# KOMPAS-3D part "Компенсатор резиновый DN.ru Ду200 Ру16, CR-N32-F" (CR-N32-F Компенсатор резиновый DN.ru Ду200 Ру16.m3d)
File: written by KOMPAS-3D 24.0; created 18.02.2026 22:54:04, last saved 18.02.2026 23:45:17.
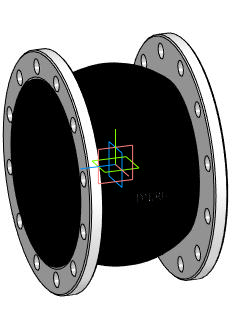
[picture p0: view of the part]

Document properties: Автор: DN.RU; Полное имя файла: D:\PROJECT CAD\DN.RU\...178(2)(ACTUALE). CR-N32-F Компенсатор резиновый DN.ru Ру10-16\CR-N32-F Компенсатор резиновый DN.ru Ру10-16\DN200_PN16\CR-N32-F Компенсатор резиновый DN.ru Ду200 Ру16.m3d

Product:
- Body: Твердое тело2  | qty 1
    Масса: 46.886983
- Part/product: Компенсатор резиновый DN.ru Ду200 Ру16  | designation CR-N32-F
    Масса: 20
    Раздел спецификации: Прочие изделия
    Комментарий: D140-02400
    Примечание: D140-02385
    additional columns: Типовые

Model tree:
1. Твердое тело2  (labels: Твердое тело2)

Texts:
  CR-N32-F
